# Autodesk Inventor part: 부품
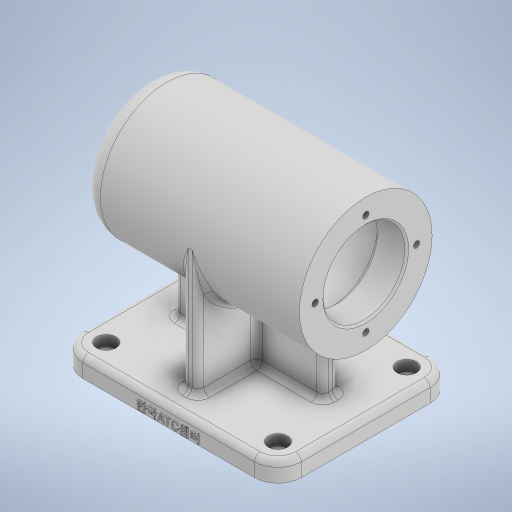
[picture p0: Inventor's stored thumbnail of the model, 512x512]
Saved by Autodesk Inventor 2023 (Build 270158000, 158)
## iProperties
Created: 2026-08
Part Number: 부품
Material: 일반
Document SubType Name: Modeling
Designer: 4강의실
Density: 1 g/cm^3
Appearance: 기본값
Mass: 379.96 g
Surface Area: 757.812 cm^2
Volume: 379.96 cm^3
Author: 4강의실
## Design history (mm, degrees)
sketch "스케치1"
  geometry: L1 (56, 45)-(-56, 45); L2 (-56, 45)-(-56, -45); L3 (-56, -45)-(56, -45); L4 (56, -45)-(56, 45); L5 (56, 45)-(-56, -45); L6 (-56, 45)-(56, -45); 1 further point
  constraints: 12 end point, 2 midpoint, 2 parallel, 1 horizontal, 1 perpendicular
  dimensions: "d0" = 112 distance of L2.end L3.end; "d1" = 90 distance of L3.end L1.start
extrude "돌출1" new body sketch "스케치1" distance "d2" = 10; taper "d3" = 0 deg
node "작업 평면1"
sketch "스케치2"
  geometry: L1 (56, 34)-(-56, 34); L2 (-56, 34)-(-56, -34); L3 (-56, -34)-(56, -34); L4 (56, -34)-(56, 34); L5 (56, 34)-(-56, -34); L6 (-56, 34)-(56, -34); L7 (-56, 0)-(56, 0); 1 further point
  constraints: 14 end point, 4 midpoint, 2 parallel, 1 horizontal, 1 perpendicular
  dimensions: "d5" = 112 distance of L2.end L3.end; "d6" = 68 diameter of L3 L7
revolve "회전1" sketch "스케치2" stored, may be unused: angle "d7" = 90 deg
sketch "스케치4"
  geometry: L1 (56, 40)-(56, 108) reference; L2 (56, 74)-(-82, 74); L3 (56, 95)-(41, 95); L4 (41, 95)-(41, 98); L5 (41, 98)-(-13, 98); L6 (-13, 98)-(-13, 95); L7 (-13, 95)-(-25, 95); L8 (-25, 95)-(-25, 91.5); L9 (-25, 91.5)-(-43, 91.5); L10 (-43, 91.5)-(-43, 90); L11 (-43, 90)-(-47, 90); L12 (-47, 90)-(-47, 84.5); L13 (-47, 84.5)-(-50, 84.5); L14 (-50, 84.5)-(-50, 74); L15 (56, 95)-(56, 74); 1 further point
  constraints: 28 end point, 9 perpendicular, 2 horizontal, 2 point on line, 1 collinear, 1 midpoint, 1 vertical
  dimensions: "d8" = 15 distance of L3.start L3.end; "d9" = 54 distance of L4.end L5.end; "d10" = 42 diameter of L3 L2; "d11" = 48 diameter of L5 L2; "d12" = 81 distance between parallel lines of L1 L8; "d13" = 21 diameter of L13 L2; "d14" = 32 diameter of L11 L2; "d15" = 35 diameter of L9 L2; "d16" = 3 distance of L12.end L13.end; "d17" = 103 distance between parallel lines of L1 L12; "d19" = 42 diameter of L7 L2; "d20" = 18 distance of L8.end L9.end
revolve "회전2" sketch "스케치4" stored, may be unused: angle "d21" = 90 deg
chamfer "모따기1" distance "d22" = 1; stored, may be unused: second distance "d23" = 2, angle "d24" = 45 deg
fillet "모깎기1" dims "d25" = 3
fillet "모깎기2" dims "d32" = 3
fillet "모깎기3" dims "d33" = 3
sketch "스케치5"
  geometry: L1 (-4, -34)-(4, -34); L2 (4, -34)-(4, 34); L3 (4, 34)-(-4, 34); L4 (-4, 34)-(-4, -34); L5 (-4, -34)-(4, 34); L6 (4, -34)-(-4, 34); L7 (-38, -4)-(38, -4); L8 (38, -4)-(38, 4); L9 (38, 4)-(-38, 4); L10 (-38, 4)-(-38, -4); L11 (-38, -4)-(38, 4); L12 (38, -4)-(-38, 4); 5 further points
  constraints: 24 end point, 4 midpoint, 4 parallel, 2 horizontal, 2 perpendicular
  dimensions: "d34" = 8 distance of L2.end L3.end; "d35" = 8 distance of L7.end L8.end; "d36" = 76 distance of L8.end L9.end; "d37" = 68 distance of L1.end L2.end
extrude "돌출2" join sketch "스케치5" stored distance "d38" = 10; taper "d39" = 0 deg
sketch "스케치7"
  geometry: C1 r 34 at (0, 0) reference; A1 r 26 centre (0, 0) between (0, 26) and (26, 0); 4 further points
  constraints: 4 point on circle, 2 horizontal alignment, 2 vertical alignment, 1 centre point, 1 coincident
  dimensions: "d47" = 52 diameter of A1
hole "구멍1" sketch "스케치7" at (0, 26), (-26, 0), (0, -26), (26, 0) diameter "d40" = 3.242; stored, may be unused: countersink angle "d44" = 90 deg, drill point angle "d46" = 118 deg; dims "d41" = 8, "d42" = 4, "d43" = 2, "d45" = 10
sketch "스케치9"
  geometry: L1 (-56, 45)-(-56, -45) reference; L2 (-56, -45)-(56, -45) reference; 8 further points
  constraints: 3 midpoint
  dimensions: "d55" = 66 distance of point (-44, 33) point (-44, -33); "d56" = 88 distance of point (44, -33) point (-44, -33); "d57" = 66 distance of point (44, 33) point (44, -33); "d58" = 88 distance of point (-44, 33) point (44, 33); "d59" = 33 vertical distance of point (-56, 0) point (-44, -33); "d60" = 44 horizontal distance of point (0, -45) point (-44, -33) (= 0.5 x d56); "d61" = 44 horizontal distance of point (0, -45) point (-44, 33); "d62" = 33 vertical distance of point (-56, 0) point (44, -33) (= 0.5 x d57)
hole "구멍2" sketch "스케치9" at (-44, -33), (44, -33), (44, 33), (-44, 33) diameter "d48" = 5.5; stored, may be unused: countersink angle "d52" = 90 deg, drill point angle "d54" = 0 deg; dims "d49" = 5.5, "d50" = 10, "d51" = 5.5, "d53" = 10
fillet "모깎기4" dims "d63" = 12
fillet "모깎기5" dims "d64" = 3
fillet "모깎기6" dims "d65" = 3
fillet "모깎기7" dims "d66" = 10
sketch "스케치10"
  geometry: L1 (0, 0)-(88, 0) reference; 4 further points
  constraints: 2 midpoint, 1 vertical alignment, 1 other
  dimensions: "d67" = 3 distance of point (44, 3) point (44, 0)
feature "엠보싱1" sketch "스케치10" dims "d8" = 15, "d9" = 54, "d10" = 42, "d11" = 48, "d12" = 81, "d13" = 21, "d14" = 32, "d15" = 35, "d16" = 3, "d17" = 103, "d19" = 42, "d20" = 18, "d68" = 0.5, "d69" = 0
fillet "모깎기8" dims "d70" = 0.6
fillet "모깎기9" dims "d71" = 0.6
node "솔리드1"
feature "A9D066F2-1C7D-4E18-AEED-F7BC21143FA4" dims "d40" = 3.242, "d41" = 8, "d42" = 4, "d43" = 2, "d44" = 90 deg, "d45" = 10, "d46" = 118 deg
other parameters: "d4" = -74
